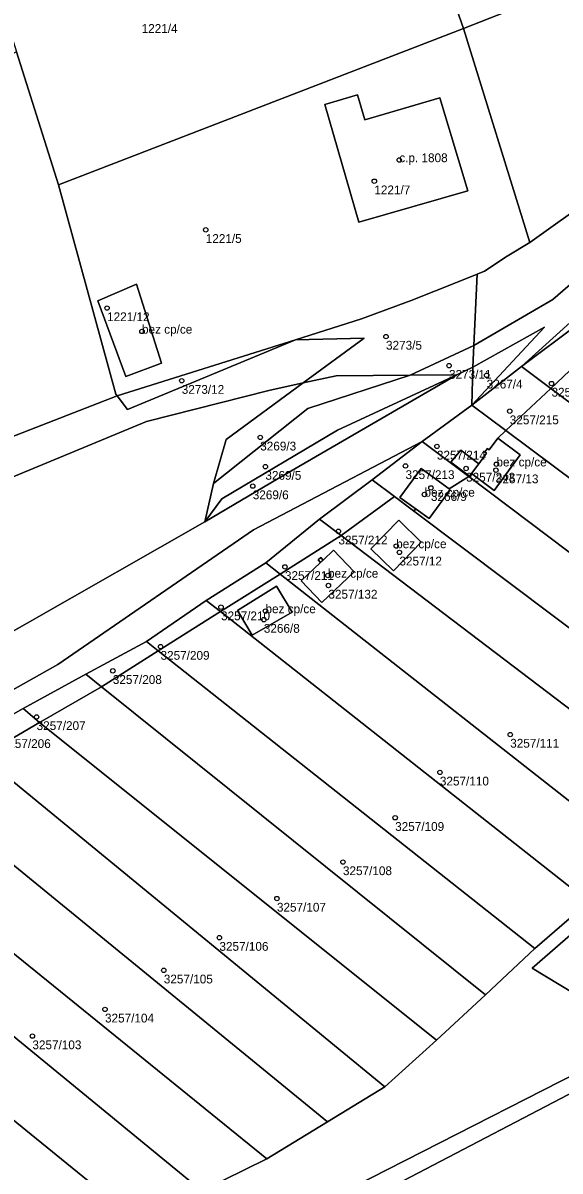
# Model space of a CAD drawing. Extents: x -878211 to -870363, y -1058464 to -1052522.
# Drawn here: x -875754.6 to -875693.5, y -1056468.6 to -1056338.1 of the extents above; entities that cross this region are included whole.
import ezdxf

# ---------------------------------------------------------------- set-up
doc = ezdxf.new("R2010")
doc.units = 0
for name, color, linetype in [('Definiční body', 7, 'Continuous'), ('Polygon budovy', 7, 'Continuous'), ('Polygon parcely', 7, 'Continuous')]:
    doc.layers.add(name, color=color, linetype=linetype)

msp = doc.modelspace()

# ---------------------------------------------------------------- linework, layer by layer
at = {"layer": 'Definiční body'}
for centre in [(-875711.79, -1056353.64994), (-875714.63, -1056356.05994), (-875733.81, -1056361.58994), (-875745.03, -1056370.47994), (-875741.06, -1056373.13994), (-875713.3, -1056373.71994), (-875706.13, -1056377.02994), (-875736.54, -1056378.73994), (-875701.85, -1056378.12994), (-875694.47, -1056379.05994), (-875699.22, -1056382.19994), (-875727.61, -1056385.17994), (-875707.51, -1056386.20994), (-875711.08, -1056388.42994), (-875700.74, -1056388.22994), (-875727.02, -1056388.50994), (-875704.19, -1056388.71994), (-875700.79, -1056388.90994), (-875728.46, -1056390.71994), (-875708.19, -1056390.91994), (-875708.92, -1056391.66994), (-875718.71, -1056395.85994), (-875712.14, -1056397.52994), (-875711.77, -1056398.24994), (-875724.8, -1056399.89994), (-875719.9, -1056400.87994), (-875719.85, -1056402.01994), (-875732.07, -1056404.47994), (-875727.01, -1056404.91994), (-875727.2, -1056405.89994), (-875738.95, -1056408.96994), (-875744.38, -1056411.71994), (-875753.05, -1056416.95994), (-875699.17, -1056418.95994), (-875707.17, -1056423.25994), (-875712.26, -1056428.41994), (-875718.2, -1056433.44994), (-875725.71, -1056437.59994), (-875732.25, -1056442.04994), (-875738.58, -1056445.75994), (-875745.27, -1056450.19994), (-875753.53, -1056453.23994)]:
    msp.add_circle(centre, 0.25, dxfattribs=at)
at = {"layer": 'Polygon budovy'}
for points in [[(-875716.55, -1056346.24), (-875720.26, -1056347.34), (-875716.41, -1056360.72), (-875703.98, -1056357.16), (-875707.19, -1056346.59), (-875715.71, -1056349.09)], [(-875741.7, -1056367.78), (-875746.09, -1056369.67), (-875742.91, -1056378.26), (-875738.84, -1056376.75)], [(-875698.03, -1056387.16), (-875700.57, -1056385.27), (-875701.56, -1056386.6), (-875701.77, -1056386.44), (-875702.06, -1056386.83), (-875701.85, -1056386.99), (-875702.74, -1056388.19), (-875704.8, -1056386.65), (-875705.92, -1056388.01), (-875703.79, -1056389.6), (-875703.56, -1056389.29), (-875701, -1056391.2)], [(-875711.72, -1056392.01), (-875709.86, -1056393.35), (-875708.4, -1056394.41), (-875705.99, -1056391.13), (-875706.12, -1056391.04), (-875709.31, -1056388.71)], [(-875715.01, -1056397.85), (-875712.44, -1056400.35), (-875709.29, -1056397.08), (-875711.85, -1056394.59)], [(-875720.46, -1056399.12), (-875720.75, -1056399.4), (-875722.94, -1056401.49), (-875720.59, -1056403.95), (-875716.91, -1056400.48), (-875719.28, -1056398)], [(-875730.2, -1056404.87), (-875728.51, -1056407.66), (-875723.96, -1056405.04), (-875725.76, -1056402.1)]]:
    msp.add_lwpolyline(points, close=True, dxfattribs=at)
at = {"layer": 'Polygon parcely'}
for points in [[(-875725.2, -1056276.37), (-875728.69, -1056278.17), (-875723.33, -1056288.66), (-875714.83, -1056309.2), (-875704.48, -1056338.69), (-875699.54, -1056336.78), (-875703.74, -1056326.61), (-875719.78, -1056287.09)], [(-875642.54, -1056321.47), (-875642.63, -1056314.95), (-875651.97, -1056298.54), (-875650.62, -1056304.44), (-875646.62, -1056318.65), (-875647.82, -1056322.26), (-875646.14, -1056324.55), (-875663.43, -1056342.76), (-875673.95, -1056351.87), (-875694.33, -1056369.52), (-875703.32, -1056374.74), (-875703.43, -1056377.18), (-875695.25, -1056372.67), (-875703.53, -1056381.51), (-875697.87, -1056377.14), (-875677.29, -1056358.5), (-875662.3, -1056346.67), (-875657.54, -1056342.8), (-875646.31, -1056329.33)], [(-875704.48, -1056338.69), (-875714.83, -1056309.2), (-875738.05, -1056317.07), (-875737.28, -1056321.06), (-875744.17, -1056326.18), (-875756.07, -1056332.11), (-875757.22, -1056335.33), (-875755.32, -1056341.37), (-875750.57, -1056356.47)], [(-875696.95, -1056363.01), (-875675.36, -1056347.63), (-875682.59, -1056329.88), (-875686.86, -1056319.7), (-875689.62, -1056320.79), (-875703.74, -1056326.61), (-875699.54, -1056336.78), (-875704.48, -1056338.69)], [(-875744.04, -1056380.27), (-875743.9, -1056380.45), (-875723.59, -1056374.09), (-875716.08, -1056371.71), (-875710.43, -1056369.63), (-875704.9, -1056367.41), (-875702.92, -1056366.62), (-875702.08, -1056366.29), (-875699.5, -1056364.57), (-875696.95, -1056363.01), (-875704.48, -1056338.69), (-875750.57, -1056356.47)], [(-875902.96, -1056439.22), (-875889.9, -1056448.83), (-875863.27, -1056435.69), (-875823.17, -1056414.73), (-875781.12, -1056394.95), (-875743.9, -1056380.45), (-875744.04, -1056380.27), (-875750.57, -1056356.47), (-875755.32, -1056341.37), (-875900.87, -1056414.26), (-875910.39, -1056420), (-875909.53, -1056423.84)], [(-875720.26, -1056347.34), (-875716.41, -1056360.72), (-875703.98, -1056357.16), (-875707.19, -1056346.59), (-875715.71, -1056349.09), (-875716.55, -1056346.24)], [(-875720.26, -1056347.34), (-875716.55, -1056346.24), (-875715.71, -1056349.09), (-875707.19, -1056346.59), (-875703.98, -1056357.16), (-875716.41, -1056360.72)], [(-875702.92, -1056366.62), (-875703.32, -1056374.74), (-875694.33, -1056369.52), (-875673.95, -1056351.87), (-875675.36, -1056347.63), (-875696.95, -1056363.01), (-875699.5, -1056364.57), (-875702.08, -1056366.29)], [(-875723.59, -1056374.09), (-875715.8, -1056373.92), (-875722.72, -1056378.99), (-875718.97, -1056378.18), (-875710.56, -1056378.09), (-875703.32, -1056374.74), (-875702.92, -1056366.62), (-875704.9, -1056367.41), (-875710.43, -1056369.63), (-875716.08, -1056371.71)], [(-875741.7, -1056367.78), (-875738.84, -1056376.75), (-875742.91, -1056378.26), (-875746.09, -1056369.67)], [(-875741.7, -1056367.78), (-875746.09, -1056369.67), (-875742.91, -1056378.26), (-875738.84, -1056376.75)], [(-875691.41, -1056372.29), (-875697.87, -1056377.14), (-875694.55, -1056379.61), (-875688.86, -1056374.26)], [(-875703.43, -1056377.18), (-875703.53, -1056381.51), (-875695.25, -1056372.67)], [(-875823.17, -1056414.73), (-875863.27, -1056435.69), (-875889.9, -1056448.83), (-875889.24, -1056449.96), (-875887.66, -1056453.48), (-875848.49, -1056431.03), (-875820.66, -1056417.69), (-875776.17, -1056398.13), (-875740.55, -1056383.38), (-875726.62, -1056379.84), (-875722.72, -1056378.99), (-875715.8, -1056373.92), (-875723.59, -1056374.09), (-875742.7, -1056382.01), (-875743.9, -1056380.45), (-875781.12, -1056394.95)], [(-875723.59, -1056374.09), (-875743.9, -1056380.45), (-875742.7, -1056382.01)], [(-875703.43, -1056377.18), (-875703.32, -1056374.74), (-875710.56, -1056378.09), (-875705.24, -1056378.08)], [(-875688.86, -1056374.26), (-875694.55, -1056379.61), (-875653.61, -1056410.02), (-875648.02, -1056405.82)], [(-875694.55, -1056379.61), (-875697.87, -1056377.14), (-875703.53, -1056381.51), (-875699.65, -1056384.4)], [(-875820.66, -1056417.69), (-875848.49, -1056431.03), (-875887.66, -1056453.48), (-875877.97, -1056475.14), (-875854.65, -1056465.25), (-875811.54, -1056444.06), (-875774.36, -1056417.8), (-875733.93, -1056394.77), (-875732.93, -1056390.42), (-875731.48, -1056385.42), (-875722.72, -1056378.99), (-875726.62, -1056379.84), (-875740.55, -1056383.38), (-875776.17, -1056398.13)], [(-875725.58, -1056389.87), (-875705.24, -1056378.08), (-875718.81, -1056384.36), (-875731.97, -1056392.17), (-875733.93, -1056394.77)], [(-875718.81, -1056384.36), (-875705.24, -1056378.08), (-875710.56, -1056378.09), (-875722.19, -1056381.89), (-875732.93, -1056390.42), (-875733.93, -1056394.77), (-875731.97, -1056392.17)], [(-875722.72, -1056378.99), (-875731.48, -1056385.42), (-875732.93, -1056390.42), (-875722.19, -1056381.89), (-875710.56, -1056378.09), (-875718.97, -1056378.18)], [(-875653.61, -1056410.02), (-875694.55, -1056379.61), (-875699.65, -1056384.4), (-875659.44, -1056414.39)], [(-875702.06, -1056386.83), (-875701.77, -1056386.44), (-875701.56, -1056386.6), (-875700.57, -1056385.27), (-875699.65, -1056384.4), (-875703.53, -1056381.51), (-875709.18, -1056385.64), (-875703.86, -1056389.64), (-875703.79, -1056389.6), (-875705.92, -1056388.01), (-875704.8, -1056386.65), (-875702.74, -1056388.19), (-875701.85, -1056386.99)], [(-875709.31, -1056388.71), (-875706.12, -1056391.04), (-875703.86, -1056389.64), (-875709.18, -1056385.64), (-875714.89, -1056390), (-875712.35, -1056391.91), (-875710.17, -1056393.54), (-875709.86, -1056393.35), (-875711.72, -1056392.01)], [(-875703.79, -1056389.6), (-875703.86, -1056389.64), (-875667.46, -1056417.05), (-875665.19, -1056418.71), (-875659.44, -1056414.39), (-875699.65, -1056384.4), (-875700.57, -1056385.27), (-875698.03, -1056387.16), (-875701, -1056391.2), (-875703.56, -1056389.29)], [(-875703.56, -1056389.29), (-875701, -1056391.2), (-875698.03, -1056387.16), (-875700.57, -1056385.27), (-875701.56, -1056386.6), (-875701.77, -1056386.44), (-875702.06, -1056386.83), (-875701.85, -1056386.99), (-875702.74, -1056388.19)], [(-875703.79, -1056389.6), (-875703.56, -1056389.29), (-875702.74, -1056388.19), (-875704.8, -1056386.65), (-875705.92, -1056388.01)], [(-875709.31, -1056388.71), (-875711.72, -1056392.01), (-875709.86, -1056393.35), (-875708.4, -1056394.41), (-875705.99, -1056391.13), (-875706.12, -1056391.04)], [(-875712.35, -1056391.91), (-875714.89, -1056390), (-875720.87, -1056394.49), (-875718.42, -1056396.35)], [(-875708.4, -1056394.41), (-875709.86, -1056393.35), (-875710.17, -1056393.54), (-875672.6, -1056421.76), (-875667.46, -1056417.05), (-875703.86, -1056389.64), (-875706.12, -1056391.04), (-875705.99, -1056391.13)], [(-875712.35, -1056391.91), (-875718.42, -1056396.35), (-875678.32, -1056426.74), (-875672.6, -1056421.76), (-875710.17, -1056393.54)], [(-875720.87, -1056394.49), (-875726.97, -1056399.45), (-875725.35, -1056400.72), (-875718.42, -1056396.35)], [(-875709.29, -1056397.08), (-875711.85, -1056394.59), (-875715.01, -1056397.85), (-875712.44, -1056400.35)], [(-875709.29, -1056397.08), (-875712.44, -1056400.35), (-875715.01, -1056397.85), (-875711.85, -1056394.59)], [(-875684.66, -1056432.63), (-875678.32, -1056426.74), (-875718.42, -1056396.35), (-875725.35, -1056400.72)], [(-875721.02, -1056399.11), (-875720.75, -1056399.4), (-875722.94, -1056401.49), (-875720.59, -1056403.95), (-875716.91, -1056400.48), (-875719.28, -1056398), (-875720.46, -1056399.12), (-875720.73, -1056398.83)], [(-875721.02, -1056399.11), (-875720.73, -1056398.83), (-875720.46, -1056399.12), (-875719.28, -1056398), (-875716.91, -1056400.48), (-875720.59, -1056403.95), (-875722.94, -1056401.49), (-875720.75, -1056399.4)], [(-875725.35, -1056400.72), (-875726.97, -1056399.45), (-875733.75, -1056403.71), (-875732.12, -1056404.99)], [(-875690.22, -1056437.99), (-875684.66, -1056432.63), (-875725.35, -1056400.72), (-875732.12, -1056404.99)], [(-875723.96, -1056405.04), (-875728.51, -1056407.66), (-875730.2, -1056404.87), (-875725.76, -1056402.1)], [(-875723.96, -1056405.04), (-875725.76, -1056402.1), (-875730.2, -1056404.87), (-875728.51, -1056407.66)], [(-875733.75, -1056403.71), (-875740.55, -1056408.4), (-875739.21, -1056409.46), (-875732.12, -1056404.99)], [(-875732.12, -1056404.99), (-875739.21, -1056409.46), (-875696.35, -1056443.28), (-875690.22, -1056437.99)], [(-875739.21, -1056409.46), (-875740.55, -1056408.4), (-875747.44, -1056412.11), (-875745.67, -1056413.53)], [(-875701.98, -1056448.55), (-875696.35, -1056443.28), (-875739.21, -1056409.46), (-875745.67, -1056413.53)], [(-875747.44, -1056412.11), (-875754.59, -1056416.01), (-875752.71, -1056417.6), (-875745.67, -1056413.53)], [(-875745.67, -1056413.53), (-875752.71, -1056417.6), (-875707.54, -1056453.71), (-875701.98, -1056448.55)], [(-875752.71, -1056417.6), (-875754.59, -1056416.01), (-875761.29, -1056419.78), (-875759.3, -1056421.42)], [(-875713.43, -1056459), (-875707.54, -1056453.71), (-875752.71, -1056417.6), (-875759.3, -1056421.42)], [(-875760.86, -1056422.32), (-875765.94, -1056425.43), (-875719.97, -1056462.99), (-875713.43, -1056459), (-875759.3, -1056421.42)], [(-875659.5, -1056440.39), (-875659.22, -1056440.19), (-875663.89, -1056433.96), (-875671.55, -1056423.73), (-875696.67, -1056445.53), (-875690.35, -1056449.36), (-875683.67, -1056453.41), (-875682.29, -1056454.52), (-875657.28, -1056444.15)], [(-875765.94, -1056425.43), (-875768.05, -1056426.72), (-875766.09, -1056428.69), (-875769.82, -1056432.39), (-875726.86, -1056467.19), (-875719.97, -1056462.99)], [(-875734.26, -1056470.83), (-875726.86, -1056467.19), (-875769.82, -1056432.39), (-875772.89, -1056429.7), (-875773.22, -1056429.91), (-875771.66, -1056431.24), (-875774.26, -1056434.3), (-875776.74, -1056432.19), (-875779.34, -1056433.88)], [(-875779.34, -1056433.88), (-875785.98, -1056438.21), (-875741.5, -1056474.31), (-875734.26, -1056470.83)], [(-875741.5, -1056474.31), (-875785.98, -1056438.21), (-875792.66, -1056442.56), (-875748.75, -1056477.85)], [(-875779.94, -1056503.64), (-875719.03, -1056473.69), (-875682.29, -1056454.52), (-875683.67, -1056453.41), (-875717, -1056470.38), (-875752.35, -1056487.54), (-875781.56, -1056501.24), (-875819.27, -1056524.13)]]:
    msp.add_lwpolyline(points, close=True, dxfattribs=at)
for points in [[(-875646.31, -1056329.33), (-875657.54, -1056342.8), (-875662.3, -1056346.67), (-875677.29, -1056358.5), (-875697.87, -1056377.14), (-875691.41, -1056372.29), (-875686.4, -1056368.63), (-875681.06, -1056364.25), (-875675.52, -1056359.72), (-875670, -1056355.32), (-875664.6, -1056350.88), (-875659.19, -1056346.43), (-875654.29, -1056341.32), (-875649.39, -1056336.33)], [(-875770.46, -1056422.13), (-875750.62, -1056411.01), (-875728.37, -1056395.68), (-875709.18, -1056385.64), (-875703.53, -1056381.51), (-875703.43, -1056377.18), (-875705.24, -1056378.08), (-875725.58, -1056389.87), (-875733.93, -1056394.77), (-875774.36, -1056417.8)], [(-875761.29, -1056419.78), (-875754.59, -1056416.01), (-875747.44, -1056412.11), (-875740.55, -1056408.4), (-875733.75, -1056403.71), (-875726.97, -1056399.45), (-875720.87, -1056394.49), (-875714.89, -1056390), (-875709.18, -1056385.64), (-875728.37, -1056395.68), (-875750.62, -1056411.01), (-875770.46, -1056422.13)], [(-875781.56, -1056501.24), (-875752.35, -1056487.54), (-875717, -1056470.38), (-875683.67, -1056453.41), (-875690.35, -1056449.36), (-875696.67, -1056445.53), (-875671.55, -1056423.73), (-875668.4, -1056421.24), (-875665.19, -1056418.71), (-875667.46, -1056417.05), (-875672.6, -1056421.76), (-875678.32, -1056426.74), (-875684.66, -1056432.63), (-875690.22, -1056437.99), (-875696.35, -1056443.28), (-875701.98, -1056448.55), (-875707.54, -1056453.71), (-875713.43, -1056459), (-875719.97, -1056462.99), (-875726.86, -1056467.19), (-875734.26, -1056470.83), (-875741.5, -1056474.31), (-875748.75, -1056477.85), (-875756.09, -1056481.43)], [(-875759.48, -1056564.16), (-875723.29, -1056542.13), (-875716.38, -1056537.2), (-875717.03, -1056535.81), (-875729.78, -1056508.48), (-875719.88, -1056502.91), (-875714.95, -1056500.14), (-875700.83, -1056492.19), (-875688.06, -1056485.53), (-875687.4, -1056483.33), (-875667.88, -1056472.85), (-875666.38, -1056472.05), (-875646, -1056464.24), (-875647.35, -1056460.95), (-875657.28, -1056444.15), (-875682.29, -1056454.52), (-875719.03, -1056473.69), (-875779.94, -1056503.64)]]:
    msp.add_lwpolyline(points, dxfattribs=at)

# ---------------------------------------------------------------- texts
at = {"layer": 'Definiční body'}
for s, p in [('1221/4', (-875741.1, -1056339.199)), ('c.p. 1808', (-875711.79, -1056353.899)), ('1221/7', (-875714.63, -1056357.549)), ('1221/5', (-875733.81, -1056363.079)), ('1221/12', (-875745.03, -1056371.969)), ('bez cp/ce', (-875741.06, -1056373.389)), ('3273/5', (-875713.3, -1056375.209)), ('3273/11', (-875706.13, -1056378.519)), ('3267/4', (-875701.85, -1056379.619)), ('3273/12', (-875736.54, -1056380.229)), ('3257/216', (-875694.47, -1056380.549)), ('3257/215', (-875699.22, -1056383.689)), ('3269/3', (-875727.61, -1056386.669)), ('3257/214', (-875707.51, -1056387.699)), ('bez cp/ce', (-875700.74, -1056388.48)), ('3269/5', (-875727.02, -1056389.999)), ('3257/213', (-875711.08, -1056389.919)), ('3257/243', (-875704.19, -1056390.209)), ('3257/13', (-875700.79, -1056390.399)), ('3269/6', (-875728.46, -1056392.209)), ('bez cp/ce', (-875708.92, -1056391.919)), ('3266/9', (-875708.19, -1056392.409)), ('3257/212', (-875718.71, -1056397.349)), ('bez cp/ce', (-875712.14, -1056397.78)), ('3257/12', (-875711.77, -1056399.739)), ('3257/211', (-875724.8, -1056401.389)), ('bez cp/ce', (-875719.9, -1056401.129)), ('3257/132', (-875719.85, -1056403.509)), ('3257/210', (-875732.07, -1056405.969)), ('bez cp/ce', (-875727.01, -1056405.169)), ('3266/8', (-875727.2, -1056407.389)), ('3257/209', (-875738.95, -1056410.459)), ('3257/208', (-875744.38, -1056413.209)), ('3257/207', (-875753.05, -1056418.449)), ('3257/206', (-875757.02, -1056420.489)), ('3257/111', (-875699.17, -1056420.449)), ('3257/110', (-875707.17, -1056424.749)), ('3257/109', (-875712.26, -1056429.909)), ('3257/108', (-875718.2, -1056434.939)), ('3257/107', (-875725.71, -1056439.089)), ('3257/106', (-875732.25, -1056443.539)), ('3257/105', (-875738.58, -1056447.249)), ('3257/104', (-875745.27, -1056451.689)), ('3257/103', (-875753.53, -1056454.729))]:
    msp.add_text(s, height=0.999996, dxfattribs=at).set_placement(p)

doc.saveas('drawing.dxf')
